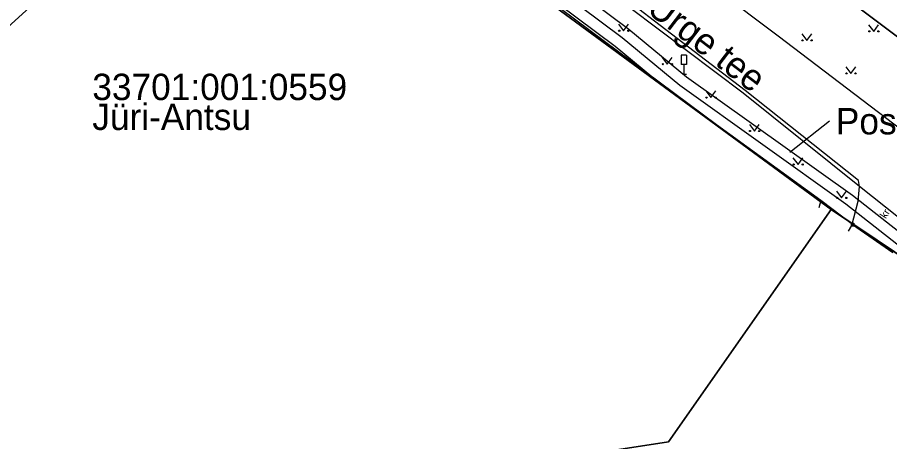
# Model space of a CAD drawing. Extents: x 554947 to 555436, y 6564938 to 6565792.
# Drawn here: x 555228.5 to 555307.9, y 6565518.6 to 6565557.2 of the extents above; entities that cross this region are included whole.
import ezdxf

# ---------------------------------------------------------------- set-up
doc = ezdxf.new("R2010")
doc.units = 0
for name, color, linetype in [('AED', 7, 'Continuous'), ('HALJASTUS', 7, 'Continuous'), ('KASUTUSALA', 7, 'Continuous'), ('LIIKLUS', 7, 'Continuous'), ('PIIR', 7, 'Continuous'), ('PR_SIDE', 7, 'Continuous'), ('TEE', 7, 'Continuous'), ('VORMISTUS_3', 7, 'Continuous')]:
    doc.layers.add(name, color=color, linetype=linetype)

msp = doc.modelspace()

# ---------------------------------------------------------------- linework, layer by layer
at = {"layer": 'AED'}
for p, q in [((555304.399, 6565538.477), (555304.399, 6565538.227)), ((555304.399, 6565538.477), (555304.649, 6565538.477)), ((555304.649, 6565538.477), (555304.649, 6565538.227)), ((555304.399, 6565538.227), (555304.649, 6565538.227)), ((555304.524, 6565538.352), (555308.195, 6565535.788))]:
    msp.add_line(p, q, dxfattribs=at)
for points in [[(555301.646, 6565540.531), (555292.158, 6565547.42), (555274.134, 6565560.859), (555261.407, 6565570.297)], [(555304.524, 6565538.352), (555301.646, 6565540.531), (555301.451, 6565539.862)]]:
    msp.add_lwpolyline(points, dxfattribs=at)
at = {"layer": 'HALJASTUS'}
for p, q in [((555283.235, 6565556.583), (555283.698, 6565555.977)), ((555283.698, 6565555.977), (555284.144, 6565556.583)), ((555305.994, 6565556.526), (555306.458, 6565555.919)), ((555306.458, 6565555.919), (555306.903, 6565556.526)), ((555299.913, 6565555.706), (555300.377, 6565555.1)), ((555300.377, 6565555.1), (555300.822, 6565555.706)), ((555287.202, 6565553.54), (555287.666, 6565552.934)), ((555287.666, 6565552.934), (555288.111, 6565553.54)), ((555303.913, 6565552.706), (555304.376, 6565552.099)), ((555304.376, 6565552.099), (555304.822, 6565552.706)), ((555291.17, 6565550.497), (555291.633, 6565549.89)), ((555291.633, 6565549.89), (555292.079, 6565550.497)), ((555295.137, 6565547.454), (555295.6, 6565546.847)), ((555295.6, 6565546.847), (555296.046, 6565547.454)), ((555299.104, 6565544.411), (555299.568, 6565543.804)), ((555299.568, 6565543.804), (555300.013, 6565544.411)), ((555303.071, 6565541.368), (555303.535, 6565540.761)), ((555303.535, 6565540.761), (555303.98, 6565541.368))]:
    msp.add_line(p, q, dxfattribs=at)
for centre in [(555283.297, 6565555.977), (555284.126, 6565555.977), (555306.057, 6565555.919), (555306.886, 6565555.919), (555299.976, 6565555.1), (555300.804, 6565555.1), (555287.265, 6565552.934), (555288.093, 6565552.934), (555303.975, 6565552.099), (555304.804, 6565552.099), (555291.232, 6565549.89), (555292.061, 6565549.89), (555295.199, 6565546.847), (555296.028, 6565546.847), (555299.166, 6565543.804), (555299.995, 6565543.804), (555303.134, 6565540.761), (555303.963, 6565540.761)]:
    msp.add_circle(centre, 0.055, dxfattribs=at)
at = {"layer": 'KASUTUSALA'}
for points in [[(555265.293, 6565570.221), (555284.174, 6565556.114), (555289.418, 6565551.775), (555304.515, 6565541.003), (555310.279, 6565536.49)], [(555330.79, 6565520.761), (555305.197, 6565537.964), (555302.6, 6565539.71), (555292.878, 6565546.85), (555287.15, 6565551.055), (555282.937, 6565554.541), (555264.078, 6565568.633)]]:
    msp.add_lwpolyline(points, dxfattribs=at)
at = {"layer": 'LIIKLUS'}
for p, q in [((555288.929, 6565553.739), (555288.929, 6565552.889)), ((555289.429, 6565553.739), (555288.929, 6565553.739)), ((555289.429, 6565553.739), (555289.429, 6565552.889)), ((555289.429, 6565552.889), (555288.929, 6565552.889)), ((555289.179, 6565552.889), (555289.179, 6565551.989)), ((555289.429, 6565551.989), (555289.179, 6565551.989))]:
    msp.add_line(p, q, dxfattribs=at)
at = {"layer": 'PIIR'}
for points in [[(555374.15, 6565660.24), (555410.9, 6565638.65), (555418.94, 6565635.85), (555435.71, 6565632.72), (555428.83, 6565620.98), (555419.65, 6565609.54), (555361.56, 6565549.57), (555350.68, 6565540.44), (555343.81, 6565536.56), (555330.71, 6565538.85), (555251.24, 6565598.48), (555234.35, 6565605.6), (555223.17, 6565668.21)], [(555144.16, 6565410.6), (555124.27, 6565454.45), (555113.82, 6565475.68), (555076.76, 6565542.38), (555065.78, 6565566.7), (555060.42, 6565583.26), (555057.22, 6565600.73), (555056.61, 6565622.91), (555063.43, 6565647.29), (555114.24, 6565634), (555129.77, 6565611.2), (555130.73, 6565621.32), (555138.66, 6565615.26), (555160.12, 6565598.86), (555193.24, 6565604.68), (555193.7, 6565602.7), (555225.47, 6565605.89), (555234.35, 6565605.6), (555251.24, 6565598.48), (555330.71, 6565538.85), (555343.81, 6565536.56), (555350.68, 6565540.44), (555361.56, 6565549.57), (555393.069, 6565582.099)], [(555393.069, 6565560.972), (555353.12, 6565523.87), (555343.14, 6565512.46), (555302.6, 6565539.71), (555242.37, 6565583.94), (555179.42, 6565586.32), (555138.98, 6565580.6), (555121.18, 6565602.26), (555116.17, 6565610.5), (555109.96, 6565624.83), (555093.56, 6565628.47), (555079.04, 6565618.4), (555074.13, 6565607.82), (555075.34, 6565593.24), (555091.74, 6565551.94), (555171.91, 6565394.64), (555191.35, 6565341.19), (555195.08, 6565294.61), (555195.28, 6565271.63), (555191.64, 6565237.48)]]:
    msp.add_lwpolyline(points, dxfattribs=at)
for points in [[(555121.18, 6565602.26), (555138.98, 6565580.6), (555179.42, 6565586.32), (555242.37, 6565583.94), (555302.6, 6565539.71), (555287.77, 6565518.56), (555207.29, 6565506.14), (555200.64, 6565496.23), (555185.97, 6565502.75), (555177.68, 6565506.44), (555171.49, 6565510.85), (555162.05, 6565514.45), (555140.65, 6565513.25), (555139.49, 6565523.98), (555139.26, 6565529.51), (555141.68, 6565537.52), (555139.64, 6565543.1), (555131.01, 6565550.06), (555126.35, 6565558.74), (555119.63, 6565564.84), (555105.26, 6565587.71), (555099.5, 6565594.91), (555116.17, 6565610.5)], [(555153.01, 6565448.47), (555161.15, 6565451.45), (555173.66, 6565456.03), (555207.29, 6565506.14), (555287.77, 6565518.56), (555302.6, 6565539.71), (555343.14, 6565512.46), (555319.44, 6565481.04), (555323.07, 6565461.26), (555312.9, 6565433.84), (555316.84, 6565372.52), (555318.72, 6565342.57), (555320.51, 6565314.61), (555303.13, 6565302.54), (555208.78, 6565303.3), (555205.15, 6565297.11), (555200.72, 6565310.3), (555206.9, 6565339.44), (555221.23, 6565376.06), (555216.83, 6565392.35), (555207.22, 6565406.57)]]:
    msp.add_lwpolyline(points, close=True, dxfattribs=at)
at = {"layer": 'PR_SIDE'}
for points in [[(555309.687, 6565535.684), (555303.916, 6565540.202), (555288.808, 6565550.982), (555283.555, 6565555.328), (555264.686, 6565569.427), (555260.485, 6565572.718), (555249.591, 6565581.395), (555244.05, 6565584.772), (555237.34, 6565587.08), (555232.399, 6565605.169), (555232.137, 6565606.132)], [(555237.34, 6565587.08), (555237.34, 6565565.16), (555226.585, 6565555.364), (555203.636, 6565543.731), (555203.636, 6565538.53), (555204.984, 6565533.828), (555204.645, 6565532.63)]]:
    msp.add_lwpolyline(points, dxfattribs=at)
at = {"layer": 'TEE'}
for points in [[(555309.906, 6565538.03), (555305.168, 6565541.808), (555305.066, 6565542.334), (555294.766, 6565550.531), (555276.823, 6565564.276), (555265.732, 6565572.927), (555259.684, 6565577.587), (555254.787, 6565581.289), (555247.931, 6565586.532), (555243.893, 6565589.125), (555239.934, 6565591.048), (555235.042, 6565592.642), (555234.652, 6565590.428), (555233.978, 6565588.723)], [(555272.683, 6565590.134), (555271.484, 6565588.076), (555270.516, 6565586.416), (555269.723, 6565584.609), (555268.981, 6565582.24), (555268.55, 6565578.954), (555269.504, 6565576.952), (555281.044, 6565568.103), (555297.768, 6565555.508), (555316.66, 6565541.129), (555323.074, 6565536.252), (555328.036, 6565533.009), (555332.837, 6565530.879), (555337.611, 6565529.695), (555343.363, 6565529.946), (555348.456, 6565531.532), (555353.801, 6565534.677), (555358.561, 6565538.499)], [(555304.166, 6565537.744), (555304.47, 6565538.257), (555305.035, 6565540.465), (555305.168, 6565541.808), (555294.581, 6565550.293), (555276.533, 6565563.926), (555265.084, 6565572.259), (555259.201, 6565577.119), (555257.995, 6565576.697)]]:
    msp.add_lwpolyline(points, dxfattribs=at)
at = {"layer": 'VORMISTUS_3'}
msp.add_line((555298.838, 6565544.939), (555302.438, 6565547.771), dxfattribs=at)

# ---------------------------------------------------------------- texts
at = {"layer": 'PIIR'}
msp.add_text('11202 Vaida-Urge tee', height=2.4, rotation=322.58974, dxfattribs=at).set_placement((555270.504, 6565569.319))
for s, p in [('33701:001:0559', (555235.33, 6565549.665)), ('Jüri-Antsu', (555235.33, 6565546.942))]:
    msp.add_text(s, height=2.4, dxfattribs=at).set_placement(p)
at = {"layer": 'TEE'}
msp.add_text('kr', height=0.7, rotation=57.34148, dxfattribs=at).set_placement((555307.557, 6565538.819))
at = {"layer": 'VORMISTUS_3'}
msp.add_text('Pos 2', height=2.4, dxfattribs=at).set_placement((555303.012, 6565546.544))

doc.saveas('drawing.dxf')
